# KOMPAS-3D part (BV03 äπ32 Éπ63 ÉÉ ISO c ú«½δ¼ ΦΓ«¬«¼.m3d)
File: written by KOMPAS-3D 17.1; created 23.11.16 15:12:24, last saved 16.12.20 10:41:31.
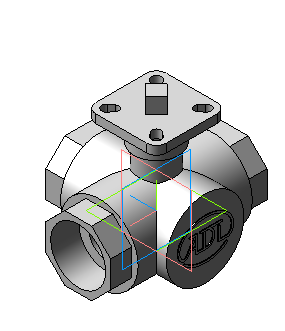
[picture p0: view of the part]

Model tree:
1. Операция без истории:1  (labels: Сталь 20  ГОСТ 1050-88)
